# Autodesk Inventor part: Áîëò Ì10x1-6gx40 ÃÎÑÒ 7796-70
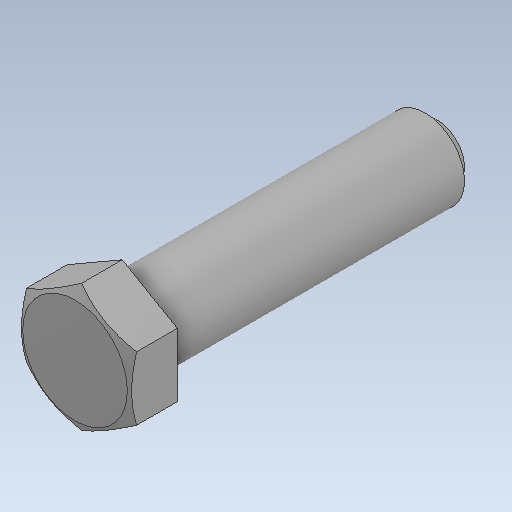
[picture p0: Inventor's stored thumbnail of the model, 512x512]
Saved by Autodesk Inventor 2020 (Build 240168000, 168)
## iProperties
Created: 1900-01
Part Number: Áîëò Ì10x1-6gx40 ÃÎÑÒ 7796-70
Material: Générique
Document SubType Name: Modeling
Designer: bruno
Density: 1 g/cm^3
Appearance: Par défaut
Author: bruno
Revision Number: ANYUNSPECIFIED
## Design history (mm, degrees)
feature "Base1"
node "Solide1"
